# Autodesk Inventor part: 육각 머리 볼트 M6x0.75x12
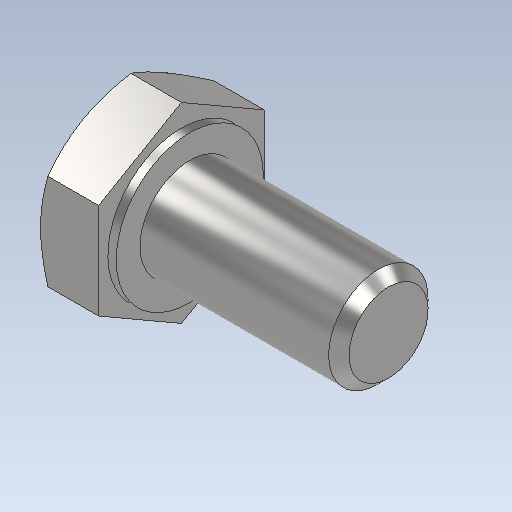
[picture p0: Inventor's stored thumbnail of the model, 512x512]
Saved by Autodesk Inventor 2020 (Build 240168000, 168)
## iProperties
Created: 2024-09
Part Number: 육각 머리 볼트 M6x0.75x12
Material: 강철, 연강
Description: 6각 머리 볼트 및 6각 머리 나사
Document SubType Name: Modeling
Designer: oem
Density: 7.85 g/cm^3
Appearance: 기본값
Author: jhkim
Sending System: Autodesk Inventor 2025
Preprocessor: ST-DEVELOPER v20
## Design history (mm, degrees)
feature "Solid1"
node "솔리드1"
